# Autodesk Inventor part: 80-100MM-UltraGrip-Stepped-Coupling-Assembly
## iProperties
Created: 2012-05
Part Number: 80-100MM-UltraGrip-Stepped-Coupling-Assembly
Document SubType Name: Modeling
Designer: D Cole
Density: 1 g/cm^3
Author: D Cole
